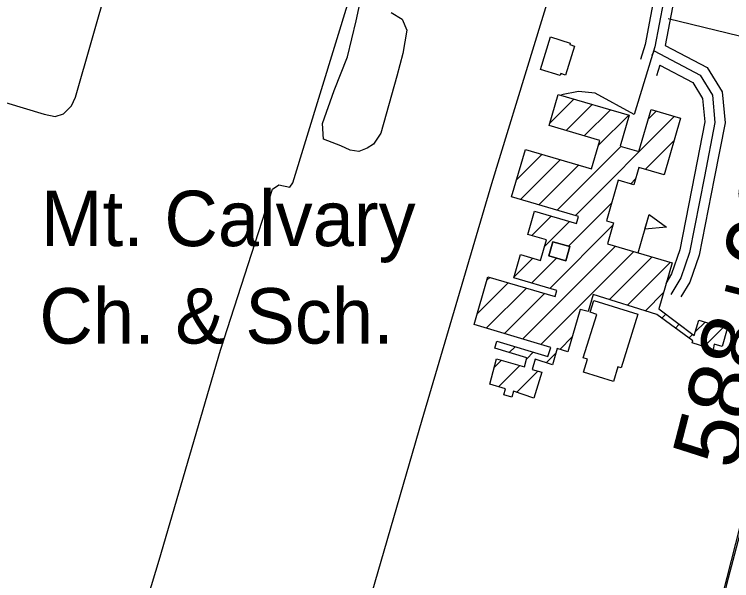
# Model space of a CAD drawing. Extents: x 3405885 to 3443815, y 558517 to 583997.
# Drawn here: x 3419685 to 3420759, y 565327 to 566174 of the extents above; entities that cross this region are included whole.
import ezdxf

# ---------------------------------------------------------------- set-up
doc = ezdxf.new("R2010")
doc.units = 0
for name, color, linetype in [('V-BLDG-OTLN', 7, 'Continuous'), ('V-DTCH-CNTR', 7, 'Continuous'), ('V-ROAD-CNTR', 7, 'Continuous'), ('V-SITE-OTLN-IDEN', 7, 'Continuous'), ('V-SITE-VEGE', 7, 'Continuous'), ('V-SURV-IDEN', 7, 'Continuous'), ('V-TOPO-SHOR', 7, 'Continuous')]:
    doc.layers.add(name, color=color, linetype=linetype)

msp = doc.modelspace()

# ---------------------------------------------------------------- linework, layer by layer
at = {"layer": 'V-BLDG-OTLN'}
for p, q in [((3420486.9, 566012.2), (3420522.4, 566047.6)), ((3420510.7, 566000.6), (3420549.7, 566039.7)), ((3420538.1, 565992.7), (3420577.1, 566031.7)), ((3420633.9, 566017.7), (3420646, 566029.8)), ((3420524.8, 565873.3), (3420673.3, 566021.8)), ((3420559.4, 565978.6), (3420604.5, 566023.7)), ((3420497.4, 565881.3), (3420593, 565976.8)), ((3420629.2, 565942.4), (3420672.6, 565985.7)), ((3420436.6, 565926.6), (3420474.9, 565964.9)), ((3420442.7, 565897.3), (3420502.3, 565956.9)), ((3420470.1, 565889.3), (3420529.7, 565948.9)), ((3420656.6, 565934.4), (3420658, 565935.8)), ((3420607.6, 565920.8), (3420614.9, 565928)), ((3420514.2, 565827.3), (3420578.9, 565892)), ((3420459.4, 565843.3), (3420488.5, 565872.4)), ((3420618.9, 565817.3), (3420635.1, 565875)), ((3420479, 565827.5), (3420515.9, 565864.4)), ((3420486.3, 565764.1), (3420580.8, 565858.6)), ((3420445.8, 565688.3), (3420585, 565827.4)), ((3420473.1, 565680.2), (3420612.3, 565819.4)), ((3420433.1, 565781.7), (3420460.9, 565809.4)), ((3420459, 565772.1), (3420496.4, 565809.6)), ((3420575.7, 565747.5), (3420639.7, 565811.4)), ((3420602.6, 565739), (3420667.1, 565803.5)), ((3420377.8, 565726.3), (3420424, 565772.5)), ((3420392.4, 565776.3), (3420396.6, 565780.5)), ((3420391.3, 565704.5), (3420451.4, 565764.5)), ((3420418.6, 565696.4), (3420478.7, 565756.5)), ((3420629.5, 565730.6), (3420656.7, 565757.8)), ((3420654.1, 565719.8), (3420660.1, 565725.7)), ((3420674.4, 565704.8), (3420680.2, 565710.5)), ((3420704.3, 565699.2), (3420718.9, 565713.8)), ((3420717.4, 565677), (3420745.8, 565705.4)), ((3420501.2, 565672.9), (3420519.7, 565691.4)), ((3420694.8, 565689.8), (3420700.3, 565695.3)), ((3420425.8, 565668.2), (3420434.4, 565676.9)), ((3420451.9, 565658.9), (3420461.6, 565668.7)), ((3420480.9, 565652.6), (3420495.4, 565667.1)), ((3420403, 565645.5), (3420414.2, 565656.6)), ((3420409.8, 565616.9), (3420441.7, 565648.8)), ((3420436.7, 565608.5), (3420468.7, 565640.4))]:
    msp.add_line(p, q, dxfattribs=at)
for points in [[(3420472.6, 566092.1), (3420487.7, 566140.6), (3420517.1, 566131.4), (3420516.4, 566129.1), (3420523.3, 566126.9), (3420509.8, 566083.6), (3420502.9, 566085.8), (3420502, 566082.9)], [(3420373, 565709.9), (3420393.9, 565781.3), (3420494.3, 565752), (3420496.9, 565761), (3420432.6, 565779.8), (3420442.8, 565814.7), (3420472.7, 565806), (3420481.7, 565836.8), (3420453.3, 565845), (3420463.4, 565879.7), (3420526.2, 565861.4), (3420529.3, 565872), (3420429.2, 565901.2), (3420449.9, 565972.1), (3420549.1, 565943.2), (3420561.5, 565985.8), (3420485.7, 566008), (3420499.2, 566054.4), (3420605.4, 566023.4), (3420591.9, 565977.2), (3420619.7, 565969), (3420638.1, 566032.1), (3420682.3, 566019.2), (3420657.5, 565934.2), (3420619.9, 565945.1), (3420612.4, 565919.4), (3420588.9, 565926.3), (3420571.1, 565865.4), (3420581.9, 565862.3), (3420572.7, 565831), (3420669.8, 565802.6), (3420649.7, 565733.6), (3420702.6, 565693.5), (3420709.3, 565716.8), (3420752.2, 565703.4), (3420744.3, 565677), (3420732.5, 565680.5), (3420730.8, 565672.8), (3420699.5, 565682.6), (3420700.6, 565685.4), (3420646.8, 565725.2), (3420551.4, 565755.1), (3420543.8, 565729.7), (3420531.7, 565732.8), (3420513.2, 565669.2), (3420497.3, 565674.1), (3420490.4, 565649.6), (3420464.3, 565658), (3420460, 565642.8), (3420474.6, 565638.8), (3420462.7, 565599.6), (3420431.9, 565610.1), (3420429.6, 565601.4), (3420417.8, 565604.6), (3420420.1, 565613.9), (3420396.5, 565620.9), (3420406.5, 565658.7), (3420448.5, 565646.9), (3420452.2, 565660.2), (3420404.1, 565674.8), (3420407.3, 565685), (3420483.7, 565662.1), (3420488.1, 565675.8)], [(3420635.1, 565875), (3420660.9, 565855.8), (3420628.8, 565852.8)], [(3420490.9, 565833.7), (3420516.3, 565826.8), (3420510.6, 565805.6), (3420485.2, 565812.7)], [(3420490.9, 565833.7), (3420485.2, 565812.7), (3420510.6, 565805.6), (3420516.3, 565826.8)], [(3420552.2, 565745.9), (3420618, 565725.6), (3420593.2, 565645.3), (3420588.5, 565646.8), (3420581.8, 565625), (3420536.9, 565638.8), (3420542.9, 565658.3), (3420536.5, 565660.3), (3420556.6, 565725.3), (3420546.8, 565728.7)]]:
    msp.add_lwpolyline(points, close=True, dxfattribs=at)
at = {"layer": 'V-DTCH-CNTR'}
for points in [[(3419671.4, 566042.5), (3419729.2, 566025.1), (3419745.9, 566021.7), (3419758.2, 566025.7), (3419770.3, 566037.6), (3419776.2, 566050.7), (3419825.4, 566221.5), (3419881.5, 566418.4), (3419937.2, 566604.8), (3420000.3, 566822.8), (3420048.5, 566981.8), (3420094.3, 567132.2), (3420106.2, 567167.2)], [(3419476.3, 563943.5), (3419504.8, 564039.1), (3419509.5, 564055.2), (3419604.4, 564379.4), (3419734.6, 564800.7), (3419819.2, 565085.2), (3419901.7, 565357.3), (3419993.2, 565671.6), (3420071.2, 565912.8), (3420081, 565919.1), (3420097.1, 565915.7), (3420101.9, 565922), (3420185.6, 566195.4), (3420293.3, 566561.8), (3420397, 566887.5), (3420431.9, 566995.6), (3420448, 567045.7)]]:
    msp.add_lwpolyline(points, dxfattribs=at)
at = {"layer": 'V-ROAD-CNTR'}
for points in [[(3420834.4, 566920.7), (3420805.9, 566832.7), (3420729.1, 566497.9), (3420669.5, 566262), (3420643.6, 566125.7), (3420612.8, 566024.7), (3420554.4, 566056.5), (3420529.2, 566059.1), (3420504.1, 566053.7)], [(3420820.1, 566925.3), (3420791.4, 566836.7), (3420714.5, 566501.4), (3420654.8, 566265.2), (3420629.1, 566129.3), (3420622.2, 566106.8)], [(3420848.6, 566916), (3420820.4, 566828.7), (3420743.7, 566494.4), (3420684.1, 566258.7), (3420659.3, 566128)], [(3420659.3, 566128), (3420722.1, 566094.9), (3420744.4, 566058.4), (3420748.9, 566011.8), (3420732.6, 565928.6), (3420709.9, 565814), (3420696.1, 565773.4), (3420682.8, 565751.4)], [(3420639.8, 566113.1), (3420642.5, 566119.9), (3420711.5, 566083.6), (3420729.8, 566053.5), (3420733.7, 566012.5), (3420717.9, 565931.5), (3420695.4, 565817.9), (3420682.4, 565779.8), (3420667.6, 565755.1)], [(3420651, 566098.5), (3420646, 566082.2)], [(3420651, 566098.5), (3420700.8, 566072.2), (3420715.2, 566048.7), (3420718.6, 566013.3), (3420703.2, 565934.4), (3420680.9, 565821.8), (3420668.7, 565786.1), (3420660, 565771.6)], [(3420945.1, 566078.3), (3420900, 565938), (3420835.5, 565640.9), (3420751, 565320.8), (3420657.9, 564940.5), (3420542.5, 564463.4), (3420449.8, 564103.8), (3420411.5, 563950.5)]]:
    msp.add_lwpolyline(points, dxfattribs=at)
at = {"layer": 'V-SITE-VEGE'}
msp.add_lwpolyline([(3420248.8, 566177.3), (3420265.3, 566167.1), (3420272.6, 566150.9), (3420266.3, 566115.9), (3420257.6, 566081.9), (3420233.7, 565996.4), (3420222.3, 565979.9), (3420213.1, 565973.9), (3420200.4, 565969), (3420187.6, 565971), (3420173.5, 565977.8), (3420147.6, 565987.7), (3420146, 566011), (3420163.7, 566060.3), (3420183.7, 566110.8), (3420196.6, 566164.6), (3420202, 566190.3)], dxfattribs=at)
at = {"layer": 'V-TOPO-SHOR'}
for points in [[(3420534.4, 566594.1), (3420467.1, 566370.4), (3420472.2, 566365.6), (3420521.9, 566348), (3420527, 566342), (3420525.9, 566334.5), (3420399.3, 565920.7), (3420295, 565566.7), (3420167.6, 565128.2), (3420052.9, 564734.4), (3419954.2, 564411.3), (3419824, 563971.8)], [(3420663.7, 566168.1), (3420875.3, 566116.6), (3420929.3, 566101), (3420932.5, 566098.6), (3420933.8, 566094.3), (3420933.2, 566091.8), (3420912.3, 565993.2), (3420865.9, 565804.6), (3420849.9, 565738.2)], [(3420845.6, 565713.2), (3420809.5, 565558.3), (3420751.6, 565331.1), (3420690.1, 565091.5)]]:
    msp.add_lwpolyline(points, dxfattribs=at)

# ---------------------------------------------------------------- texts
at = {"layer": 'V-SITE-OTLN-IDEN'}
for s, p in [('Mt. Calvary', (3419724.4, 565827.4)), ('Ch. & Sch.', (3419722.2, 565681.5))]:
    msp.add_text(s, height=83, dxfattribs=at).set_placement(p)
at = {"layer": 'V-SURV-IDEN'}
msp.add_text('588+92.1', height=100, rotation=75.5403, dxfattribs=at).set_placement((3420765.3, 565490.1))

doc.saveas('drawing.dxf')
